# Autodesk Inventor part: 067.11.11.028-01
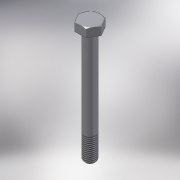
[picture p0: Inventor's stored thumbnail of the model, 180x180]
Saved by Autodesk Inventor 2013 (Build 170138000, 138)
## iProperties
Shininess: 64.0
Angle Display Precision: 2
Document Length Units: 11269
Document Angle Units: 11279
Document Time Units: 11290
Document Mass Units: 11283
Document Length Units Precision: 3
Document Angle Units Precision: 2
Created: 2003-03
Part Number: 067.11.11.028-01
Document SubType Name: Modeling
Designer: HKostya
Material: Steel, Mild
Density: 7.86 g/cm^3
Density: 0.0
Volumn: 0.0
Area: 0.0
PropertySet Name: Model Information
Control State: 0
Master: False
Checked Out: False
Checked Out Date: 2008-10-15
Last Check In Date: 2008-10-15
Author: HKostya
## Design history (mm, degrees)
sketch "Sketch3"
  geometry: L1 (0, 13.407)-(0, 23.407); L2 (0, 23.407)-(5.774, 23.407); L3 (5.774, 23.407)-(0, 13.407); L4 (0, 9.815)-(0, 0) reference; L5 (129, 4.907)-(-21.5, 4.907) reference
  constraints: 6 end point, 1 horizontal, 1 vertical
  dimensions: "d12" = 10 distance of L1.start L1.end; "d13" = 30 deg angle of L1 L3; "d14" = 0 distance between parallel lines of L1 L4; "d15" = 8.5 distance from line of L5 L1.start
body "Solid1"
sketch "Sketch1"
  geometry: C1 r 5 at (-15.306, 10.482)
  constraints: 1 centre point, 1 other
  dimensions: "d0" = 10 diameter of C1
sketch "Sketch2"
  geometry: L1 (4.907, -8.5)-(-4.907, -8.5); L2 (-4.907, -8.5)-(-9.815, 0); L3 (-9.815, 0)-(-4.907, 8.5); L4 (-4.907, 8.5)-(4.907, 8.5); L5 (4.907, 8.5)-(9.815, 0); L6 (9.815, 0)-(4.907, -8.5); C1 r 5 at (0, 0) reference; 1 further point
  constraints: 12 end point, 1 coincident, 1 horizontal, 11 other
  dimensions: "d3" = 17 distance between parallel lines of L5 L2
extrude "Extrusion1" new body sketch "Sketch1" distance "d1" = 100; taper "d2" = 0 deg
extrude "Extrusion2" join sketch "Sketch2" distance "d4" = 7.5; taper "d5" = 0 deg
chamfer "Chamfer1" distance "d6" = 1.6; stored, may be unused: second distance "d7" = 1.6, angle "d17" = 45 deg
fillet "Fillet1" dims "d8" = 0.2
thread "Thread1" dims "d9" = 20, "d10" = 0
workplane "Work Plane1"
workaxis "Work Axis1"
revolve "Revolution1" stored, may be unused: angle "d16" = 90 deg
other parameters: "d11" = -8.5
